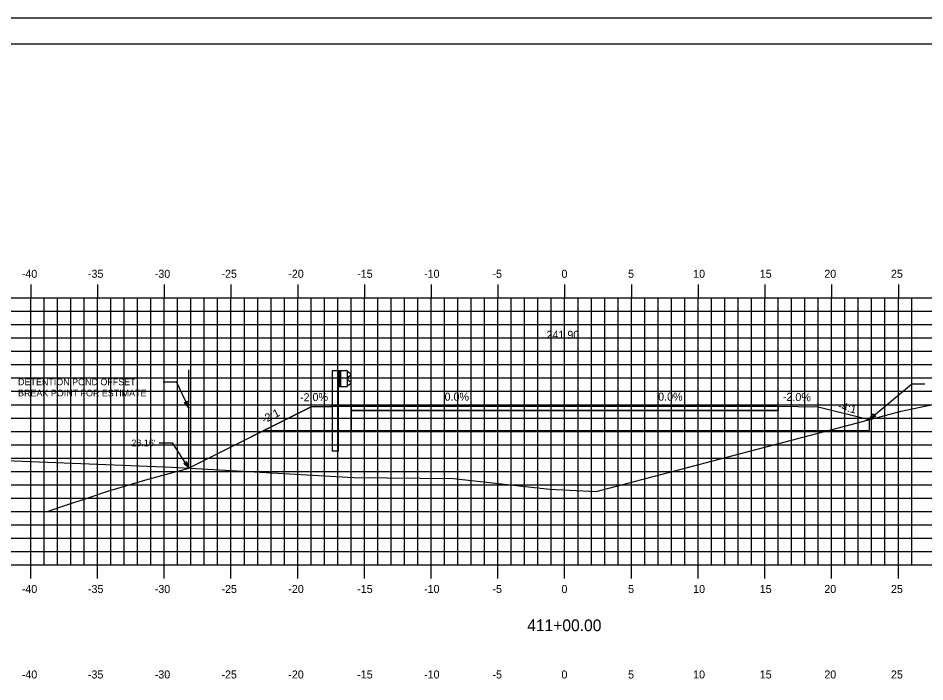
# Model space of a CAD drawing. Extents: x 1160718 to 1173142, y 616002 to 617630.
# Drawn here: x 1167703.9 to 1167771.8, y 616674.2 to 616723.9 of the extents above; entities that cross this region are included whole.
import ezdxf

# ---------------------------------------------------------------- set-up
doc = ezdxf.new("R2010")
doc.units = 0
for name, color, linetype in [('ANNOTATION', 7, 'Continuous'), ('BORDER', 7, 'Continuous'), ('D_Guardrail_Beam_Lt', 7, 'Continuous'), ('D_Roadway_Centerline', 7, 'Continuous'), ('D_Roadway_Centerline_Text', 7, 'Continuous'), ('D_Roadway_Edge_Pavement', 7, 'Continuous'), ('D_Roadway_Edge_Shoulder', 7, 'Continuous'), ('D_Roadway_Edge_TW', 7, 'Continuous'), ('D_Roadway_Pavement', 7, 'Continuous'), ('D_Roadway_SlopeLines', 7, 'Continuous'), ('D_Roadway_SubGrade', 7, 'Continuous'), ('H_V ANNOTATION', 7, 'Continuous'), ('MAJOR', 7, 'Continuous'), ('MINOR', 7, 'Continuous'), ('PLOT BOUNDARY', 7, 'Continuous'), ('S_Roadway_Centerline', 7, 'Continuous'), ('SHADING', 7, 'Continuous')]:
    doc.layers.add(name, color=color, linetype=linetype)

msp = doc.modelspace()

# ---------------------------------------------------------------- linework, layer by layer
at = {"layer": 'ANNOTATION'}
for p, q in [((1167714.758, 616696.634), (1167715.758, 616696.634)), ((1167716.661, 616694.693), (1167715.758, 616696.634)), ((1167767.646, 616693.815), (1167770.805, 616696.46)), ((1167771.805, 616696.46), (1167770.805, 616696.46)), ((1167714.435, 616692.063), (1167715.435, 616692.063)), ((1167716.661, 616690.186), (1167715.435, 616692.063))]:
    msp.add_line(p, q, dxfattribs=at)
for points in [[(1167716.563, 616695.199), (1167716.661, 616694.693), (1167716.337, 616695.094)], [(1167768.109, 616694.04), (1167767.646, 616693.815), (1167767.949, 616694.232)], [(1167716.492, 616690.673), (1167716.661, 616690.186), (1167716.283, 616690.536)]]:
    msp.add_lwpolyline(points, close=True, dxfattribs=at)
at = {"layer": 'BORDER'}
msp.add_line((1167829.829, 616721.928), (1167669.829, 616721.928), dxfattribs=at)
at = {"layer": 'D_Guardrail_Beam_Lt'}
for p, q in [((1167727.399, 616697.46), (1167727.399, 616691.46)), ((1167727.87, 616697.46), (1167727.399, 616697.46)), ((1167728.558, 616697.46), (1167727.87, 616697.46)), ((1167727.87, 616697.46), (1167727.87, 616696.293)), ((1167727.933, 616697.46), (1167727.933, 616696.293)), ((1167728.037, 616697.46), (1167728.037, 616696.293)), ((1167728.558, 616696.293), (1167728.558, 616697.46)), ((1167728.558, 616697.376), (1167728.632, 616697.362)), ((1167728.562, 616696.911), (1167728.562, 616696.841)), ((1167728.791, 616697.112), (1167728.596, 616696.976)), ((1167728.648, 616697.355), (1167728.791, 616697.255)), ((1167727.87, 616696.293), (1167728.558, 616696.293)), ((1167727.891, 616691.46), (1167727.891, 616696.293)), ((1167728.632, 616696.391), (1167728.558, 616696.376)), ((1167728.596, 616696.777), (1167728.791, 616696.641)), ((1167728.791, 616696.498), (1167728.648, 616696.398)), ((1167727.891, 616691.46), (1167727.399, 616691.46))]:
    msp.add_line(p, q, dxfattribs=at)
for centre, major_axis, start_param, end_param in [((1167728.641, 616696.911), (-0.0789, 0), 5.323254, 6.283185), ((1167728.624, 616697.321), (0.0417, 0), 0.959931, 1.376053), ((1167728.741, 616697.184), (0.0877, 0), 5.323254, 7.243116), ((1167728.641, 616696.841), (-0.0789, 0), 6.283185, 7.243116), ((1167728.624, 616696.432), (0.0417, 0), 4.907132, 5.323254), ((1167728.741, 616696.569), (0.0877, 0), 5.323254, 7.243116)]:
    msp.add_ellipse(centre, major_axis=major_axis, ratio=0.995501, start_param=start_param, end_param=end_param, dxfattribs=at)
at = {"layer": 'D_Roadway_Centerline'}
msp.add_lwpolyline([(1167716.699, 616690.204), (1167721.282, 616692.496), (1167725.829, 616694.769), (1167728.829, 616694.829), (1167744.829, 616694.829), (1167760.829, 616694.829), (1167763.829, 616694.769), (1167767.646, 616693.815)], dxfattribs=at)
at = {"layer": 'D_Roadway_Edge_Pavement'}
msp.add_lwpolyline([(1167674.829, 616686.928), (1167679.86, 616686.928), (1167680.459, 616686.928), (1167706.049, 616686.928), (1167707.605, 616687.447), (1167709.05, 616687.928), (1167710.603, 616688.446), (1167712.192, 616688.928), (1167713.453, 616689.301), (1167716.661, 616690.186)], dxfattribs=at)
at = {"layer": 'D_Roadway_Edge_Shoulder'}
for points in [[(1167728.829, 616694.829), (1167728.829, 616694.496)], [(1167760.829, 616694.829), (1167760.829, 616694.496)]]:
    msp.add_lwpolyline(points, dxfattribs=at)
at = {"layer": 'D_Roadway_Edge_TW'}
msp.add_lwpolyline([(1167760.829, 616694.496), (1167760.829, 616694.829), (1167744.829, 616694.829), (1167728.829, 616694.829), (1167728.829, 616694.496), (1167744.829, 616694.496)], close=True, dxfattribs=at)
at = {"layer": 'D_Roadway_Pavement'}
msp.add_line((1167716.661, 616690.186), (1167716.661, 616697.542), dxfattribs=at)
msp.add_lwpolyline([(1167760.829, 616694.496), (1167760.829, 616694.496), (1167744.829, 616694.496), (1167728.829, 616694.496), (1167728.829, 616694.496), (1167744.829, 616694.496)], close=True, dxfattribs=at)
for points in [[(1167728.829, 616694.496), (1167728.829, 616694.496)], [(1167728.829, 616694.496), (1167728.829, 616694.496)], [(1167760.829, 616694.496), (1167760.829, 616694.496)], [(1167760.829, 616694.496), (1167760.829, 616694.496)]]:
    msp.add_lwpolyline(points, dxfattribs=at)
at = {"layer": 'D_Roadway_SlopeLines'}
for points in [[(1167725.829, 616694.769), (1167716.661, 616690.186)], [(1167763.829, 616694.769), (1167767.646, 616693.815)]]:
    msp.add_lwpolyline(points, dxfattribs=at)
at = {"layer": 'D_Roadway_SubGrade'}
for p, q in [((1167725.829, 616694.769), (1167721.282, 616692.496)), ((1167728.829, 616694.829), (1167725.829, 616694.769)), ((1167728.829, 616692.996), (1167728.829, 616694.829)), ((1167744.829, 616694.496), (1167728.829, 616694.496)), ((1167728.829, 616694.496), (1167728.829, 616692.996)), ((1167760.829, 616694.496), (1167744.829, 616694.496)), ((1167760.829, 616694.829), (1167763.829, 616694.769)), ((1167760.829, 616692.996), (1167760.829, 616694.829)), ((1167760.829, 616692.996), (1167760.829, 616694.496)), ((1167763.829, 616694.769), (1167767.646, 616693.815)), ((1167767.646, 616693.815), (1167767.646, 616692.996))]:
    msp.add_line(p, q, dxfattribs=at)
at = {"layer": 'MAJOR'}
for p, q in [((1167704.829, 616703.93), (1167704.829, 616702.928)), ((1167709.829, 616703.93), (1167709.829, 616702.928)), ((1167714.829, 616703.93), (1167714.829, 616702.928)), ((1167719.829, 616703.93), (1167719.829, 616702.928)), ((1167724.829, 616703.93), (1167724.829, 616702.928)), ((1167729.829, 616703.93), (1167729.829, 616702.928)), ((1167734.829, 616703.93), (1167734.829, 616702.928)), ((1167739.829, 616703.93), (1167739.829, 616702.928)), ((1167744.829, 616703.93), (1167744.829, 616702.928)), ((1167749.829, 616703.93), (1167749.829, 616702.928)), ((1167754.829, 616703.93), (1167754.829, 616702.928)), ((1167759.829, 616703.93), (1167759.829, 616702.928)), ((1167764.829, 616703.93), (1167764.829, 616702.928)), ((1167769.829, 616703.93), (1167769.829, 616702.928)), ((1167674.829, 616702.928), (1167814.829, 616702.928)), ((1167674.829, 616702.928), (1167814.829, 616702.928)), ((1167704.829, 616682.928), (1167704.829, 616702.928)), ((1167709.829, 616682.928), (1167709.829, 616702.928)), ((1167714.829, 616682.928), (1167714.829, 616702.928)), ((1167719.829, 616682.928), (1167719.829, 616702.928)), ((1167724.829, 616682.928), (1167724.829, 616702.928)), ((1167729.829, 616682.928), (1167729.829, 616702.928)), ((1167734.829, 616682.928), (1167734.829, 616702.928)), ((1167739.829, 616682.928), (1167739.829, 616702.928)), ((1167744.829, 616682.928), (1167744.829, 616702.928)), ((1167749.829, 616682.928), (1167749.829, 616702.928)), ((1167754.829, 616682.928), (1167754.829, 616702.928)), ((1167759.829, 616682.928), (1167759.829, 616702.928)), ((1167764.829, 616682.928), (1167764.829, 616702.928)), ((1167769.829, 616682.928), (1167769.829, 616702.928)), ((1167674.829, 616697.928), (1167814.829, 616697.928)), ((1167674.829, 616692.928), (1167814.829, 616692.928)), ((1167674.829, 616687.928), (1167814.829, 616687.928)), ((1167674.829, 616682.928), (1167814.829, 616682.928)), ((1167674.829, 616682.928), (1167814.829, 616682.928)), ((1167704.829, 616681.926), (1167704.829, 616682.928)), ((1167709.829, 616681.926), (1167709.829, 616682.928)), ((1167714.829, 616681.926), (1167714.829, 616682.928)), ((1167719.829, 616681.926), (1167719.829, 616682.928)), ((1167724.829, 616681.926), (1167724.829, 616682.928)), ((1167729.829, 616681.926), (1167729.829, 616682.928)), ((1167734.829, 616681.926), (1167734.829, 616682.928)), ((1167739.829, 616681.926), (1167739.829, 616682.928)), ((1167744.829, 616681.926), (1167744.829, 616682.928)), ((1167749.829, 616681.926), (1167749.829, 616682.928)), ((1167754.829, 616681.926), (1167754.829, 616682.928)), ((1167759.829, 616681.926), (1167759.829, 616682.928)), ((1167764.829, 616681.926), (1167764.829, 616682.928)), ((1167769.829, 616681.926), (1167769.829, 616682.928))]:
    msp.add_line(p, q, dxfattribs=at)
at = {"layer": 'MINOR'}
for p, q in [((1167705.829, 616682.928), (1167705.829, 616702.928)), ((1167706.829, 616682.928), (1167706.829, 616702.928)), ((1167707.829, 616682.928), (1167707.829, 616702.928)), ((1167708.829, 616682.928), (1167708.829, 616702.928)), ((1167710.829, 616682.928), (1167710.829, 616702.928)), ((1167711.829, 616682.928), (1167711.829, 616702.928)), ((1167712.829, 616682.928), (1167712.829, 616702.928)), ((1167713.829, 616682.928), (1167713.829, 616702.928)), ((1167715.829, 616682.928), (1167715.829, 616702.928)), ((1167716.829, 616682.928), (1167716.829, 616702.928)), ((1167717.829, 616682.928), (1167717.829, 616702.928)), ((1167718.829, 616682.928), (1167718.829, 616702.928)), ((1167720.829, 616682.928), (1167720.829, 616702.928)), ((1167721.829, 616682.928), (1167721.829, 616702.928)), ((1167722.829, 616682.928), (1167722.829, 616702.928)), ((1167723.829, 616682.928), (1167723.829, 616702.928)), ((1167725.829, 616682.928), (1167725.829, 616702.928)), ((1167726.829, 616682.928), (1167726.829, 616702.928)), ((1167727.829, 616682.928), (1167727.829, 616702.928)), ((1167728.829, 616682.928), (1167728.829, 616702.928)), ((1167730.829, 616682.928), (1167730.829, 616702.928)), ((1167731.829, 616682.928), (1167731.829, 616702.928)), ((1167732.829, 616682.928), (1167732.829, 616702.928)), ((1167733.829, 616682.928), (1167733.829, 616702.928)), ((1167735.829, 616682.928), (1167735.829, 616702.928)), ((1167736.829, 616682.928), (1167736.829, 616702.928)), ((1167737.829, 616682.928), (1167737.829, 616702.928)), ((1167738.829, 616682.928), (1167738.829, 616702.928)), ((1167740.829, 616682.928), (1167740.829, 616702.928)), ((1167741.829, 616682.928), (1167741.829, 616702.928)), ((1167742.829, 616682.928), (1167742.829, 616702.928)), ((1167743.829, 616682.928), (1167743.829, 616702.928)), ((1167745.829, 616682.928), (1167745.829, 616702.928)), ((1167746.829, 616682.928), (1167746.829, 616702.928)), ((1167747.829, 616682.928), (1167747.829, 616702.928)), ((1167748.829, 616682.928), (1167748.829, 616702.928)), ((1167750.829, 616682.928), (1167750.829, 616702.928)), ((1167751.829, 616682.928), (1167751.829, 616702.928)), ((1167752.829, 616682.928), (1167752.829, 616702.928)), ((1167753.829, 616682.928), (1167753.829, 616702.928)), ((1167755.829, 616682.928), (1167755.829, 616702.928)), ((1167756.829, 616682.928), (1167756.829, 616702.928)), ((1167757.829, 616682.928), (1167757.829, 616702.928)), ((1167758.829, 616682.928), (1167758.829, 616702.928)), ((1167760.829, 616682.928), (1167760.829, 616702.928)), ((1167761.829, 616682.928), (1167761.829, 616702.928)), ((1167762.829, 616682.928), (1167762.829, 616702.928)), ((1167763.829, 616682.928), (1167763.829, 616702.928)), ((1167765.829, 616682.928), (1167765.829, 616702.928)), ((1167766.829, 616682.928), (1167766.829, 616702.928)), ((1167767.829, 616682.928), (1167767.829, 616702.928)), ((1167768.829, 616682.928), (1167768.829, 616702.928)), ((1167770.829, 616682.928), (1167770.829, 616702.928)), ((1167674.829, 616701.928), (1167814.829, 616701.928)), ((1167674.829, 616700.928), (1167814.829, 616700.928)), ((1167674.829, 616699.928), (1167814.829, 616699.928)), ((1167674.829, 616698.928), (1167814.829, 616698.928)), ((1167674.829, 616696.928), (1167814.829, 616696.928)), ((1167674.829, 616695.928), (1167814.829, 616695.928)), ((1167674.829, 616694.928), (1167814.829, 616694.928)), ((1167674.829, 616693.928), (1167814.829, 616693.928)), ((1167674.829, 616691.928), (1167814.829, 616691.928)), ((1167674.829, 616690.928), (1167814.829, 616690.928)), ((1167674.829, 616689.928), (1167814.829, 616689.928)), ((1167674.829, 616688.928), (1167814.829, 616688.928)), ((1167674.829, 616686.928), (1167814.829, 616686.928)), ((1167674.829, 616685.928), (1167814.829, 616685.928)), ((1167674.829, 616684.928), (1167814.829, 616684.928)), ((1167674.829, 616683.928), (1167814.829, 616683.928))]:
    msp.add_line(p, q, dxfattribs=at)
at = {"layer": 'PLOT BOUNDARY'}
msp.add_lwpolyline([(1167661.735, 616613.869), (1167831.735, 616613.869), (1167831.735, 616723.869), (1167661.735, 616723.869)], close=True, dxfattribs=at)
at = {"layer": 'S_Roadway_Centerline'}
msp.add_lwpolyline([(1167674.829, 616692.233), (1167676.59, 616692.117), (1167687.757, 616691.522), (1167702.317, 616690.786), (1167715.437, 616690.255), (1167729.036, 616689.479), (1167736.496, 616689.394), (1167743.692, 616688.596), (1167747.177, 616688.418), (1167766.658, 616693.553), (1167770.052, 616694.454), (1167771.815, 616694.807), (1167772.326, 616694.926)], dxfattribs=at)
at = {"layer": 'SHADING'}
msp.add_line((1167722.282, 616692.996), (1167767.646, 616692.996), dxfattribs=at)

# ---------------------------------------------------------------- texts
at = {"layer": 'ANNOTATION'}
for s, p in [('DETENTION POND OFFSET', (1167703.878, 616696.384)), ('BREAK POINT FOR ESTIMATE', (1167703.878, 616695.549)), ("28.16'", (1167712.367, 616691.813))]:
    msp.add_text(s, height=0.5, dxfattribs=at).set_placement(p)
for s, rotation, p in [('-2.0%', 1.14576, (1167725.008, 616695.175)), ('0.0%', 360, (1167735.833, 616695.229)), ('0.0%', 360, (1167751.833, 616695.229)), ('-2.0%', 358.85424, (1167761.172, 616695.223)), ('-4:1', 345.96376, (1167765.264, 616694.591)), ('-2:1', 26.56505, (1167722.31, 616693.503))]:
    msp.add_text(s, height=0.6, rotation=rotation, dxfattribs=at).set_placement(p)
at = {"layer": 'D_Roadway_Centerline'}
for s, p in [('C', (1167744.823, 616694.829)), ('L', (1167744.829, 616694.822))]:
    msp.add_text(s, height=0.0146, dxfattribs=at).set_placement(p)
at = {"layer": 'D_Roadway_Centerline_Text'}
msp.add_text('241.90', height=0.6, dxfattribs=at).set_placement((1167743.469, 616699.861))
at = {"layer": 'H_V ANNOTATION'}
for s, height, p in [('-40', 0.6, (1167704.154, 616704.428)), ('-35', 0.6, (1167709.109, 616704.428)), ('-30', 0.6, (1167714.117, 616704.428)), ('-25', 0.6, (1167719.114, 616704.428)), ('-20', 0.6, (1167724.122, 616704.428)), ('-15', 0.6, (1167729.285, 616704.428)), ('-10', 0.6, (1167734.293, 616704.428)), ('-5', 0.6, (1167739.419, 616704.428)), ('0', 0.6, (1167744.588, 616704.428)), ('5', 0.6, (1167749.58, 616704.428)), ('10', 0.6, (1167754.454, 616704.428)), ('15', 0.6, (1167759.446, 616704.428)), ('20', 0.6, (1167764.283, 616704.428)), ('25', 0.6, (1167769.274, 616704.428)), ('-40', 0.6, (1167704.154, 616680.828)), ('-35', 0.6, (1167709.109, 616680.828)), ('-30', 0.6, (1167714.117, 616680.828)), ('-25', 0.6, (1167719.114, 616680.828)), ('-20', 0.6, (1167724.122, 616680.828)), ('-15', 0.6, (1167729.285, 616680.828)), ('-10', 0.6, (1167734.293, 616680.828)), ('-5', 0.6, (1167739.419, 616680.828)), ('0', 0.6, (1167744.588, 616680.828)), ('5', 0.6, (1167749.58, 616680.828)), ('10', 0.6, (1167754.454, 616680.828)), ('15', 0.6, (1167759.446, 616680.828)), ('20', 0.6, (1167764.283, 616680.828)), ('25', 0.6, (1167769.274, 616680.828)), ('411+00.00', 0.875, (1167742.02, 616677.971)), ('-40', 0.6, (1167704.154, 616674.428)), ('-35', 0.6, (1167709.109, 616674.428)), ('-30', 0.6, (1167714.117, 616674.428)), ('-25', 0.6, (1167719.114, 616674.428)), ('-20', 0.6, (1167724.122, 616674.428)), ('-15', 0.6, (1167729.285, 616674.428)), ('-10', 0.6, (1167734.293, 616674.428)), ('-5', 0.6, (1167739.419, 616674.428)), ('0', 0.6, (1167744.588, 616674.428)), ('5', 0.6, (1167749.58, 616674.428)), ('10', 0.6, (1167754.454, 616674.428)), ('15', 0.6, (1167759.446, 616674.428)), ('20', 0.6, (1167764.283, 616674.428)), ('25', 0.6, (1167769.274, 616674.428))]:
    msp.add_text(s, height=height, dxfattribs=at).set_placement(p)

doc.saveas('drawing.dxf')
